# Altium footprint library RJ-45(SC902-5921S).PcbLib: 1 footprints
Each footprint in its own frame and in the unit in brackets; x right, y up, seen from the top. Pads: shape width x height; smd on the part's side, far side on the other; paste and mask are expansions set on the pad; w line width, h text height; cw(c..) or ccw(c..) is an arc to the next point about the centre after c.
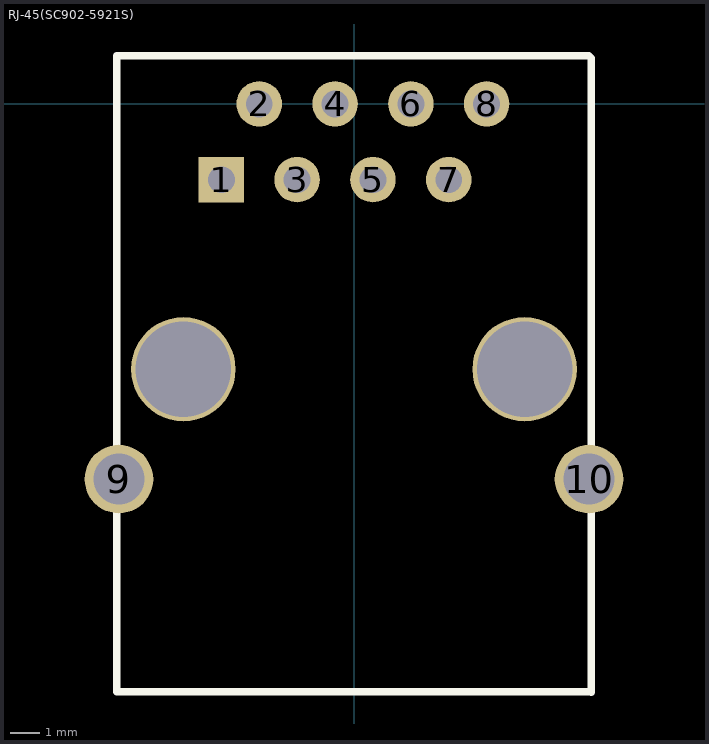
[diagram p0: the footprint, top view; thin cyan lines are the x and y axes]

## RJ-45(SC902-5921S) [mm] "RJ-45(SC902-5921S)"
pads (12):
  rect 1.524x1.524 hole 0.9: 1(-4.445,-2.54)
  round 1.524 hole 0.9: 2(-3.175,0) 3(-1.905,-2.54) 4(-0.635,0) 5(0.635,-2.54) 6(1.905,0) 7(3.175,-2.54) 8(4.445,0)
  round 2.3 hole 1.7: 9(-7.875,-12.57) 10(7.875,-12.57)
  round 3.5 hole 3.2: ""(-5.715,-8.89) ""(5.715,-8.89)
Top Overlay:
  lines w0.254: -7.95,-19.69 7.95,-19.69 ; -7.95,-19.66 -7.95,-3.861 ; -7.925,1.61 7.864,1.61 7.95,1.524 7.95,-4.369 ; 7.95,-19.71 7.95,-3.886 ; -7.95,-4.369 -7.95,1.61 -7.95,-4.369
